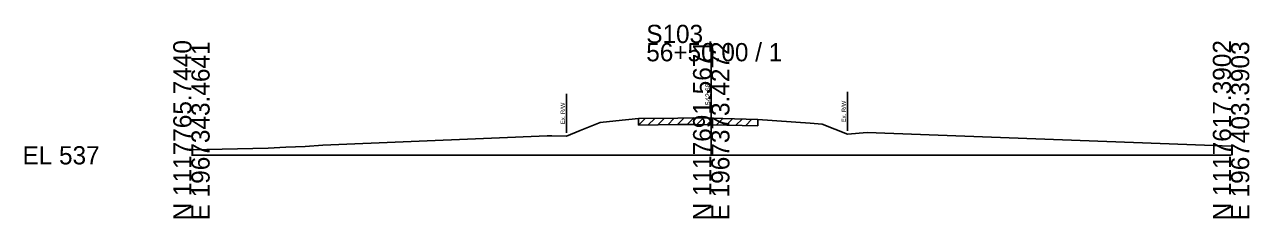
# Model space of a CAD drawing. Extents: x -26 to 163, y -10 to 24018.
# Drawn here: x -25.7 to 162.8, y 5990.3 to 6020.1 of the extents above; entities that cross this region are included whole.
import ezdxf

# ---------------------------------------------------------------- set-up
doc = ezdxf.new("R2010")
doc.units = 0
for name, color, linetype in [('RD_GPK_XS_Cell', 7, 'Continuous'), ('RD_XS_ExGround', 7, 'Continuous'), ('RD_XS_ExPaveRet', 7, 'Continuous'), ('RD_XS_ExRW', 7, 'Continuous'), ('RD_XS_TX_Elev_EX', 7, 'Continuous')]:
    doc.layers.add(name, color=color, linetype=linetype)

msp = doc.modelspace()

# ---------------------------------------------------------------- linework, layer by layer
at = {"layer": 'RD_GPK_XS_Cell'}
for p, q in [((80, 6000), (80, 6017.23)), ((0, 6000), (80, 6000)), ((80, 6000), (160, 6000))]:
    msp.add_line(p, q, dxfattribs=at)
at = {"layer": 'RD_XS_ExGround'}
msp.add_lwpolyline([(0, 6000.86), (11.83, 6001.11), (14.52, 6001.23), (17.5, 6001.37), (20.23, 6001.53), (46.18, 6002.64), (54.73, 6003.01), (55.47, 6003), (57.73, 6002.94), (59.85, 6003.83), (62.93, 6005.03), (65.32, 6005.27), (68.8, 6005.64), (74.88, 6005.72), (77.31, 6005.74), (79.53, 6005.7), (80, 6005.68), (87.19, 6005.52), (95.23, 6004.93), (97.05, 6004.8), (100.98, 6003.24), (104.02, 6003.48), (160, 6001.41)], dxfattribs=at)
at = {"layer": 'RD_XS_ExPaveRet'}
for p, q in [((68.8, 6004.64), (69.81, 6005.65)), ((68.8, 6004.64), (68.8, 6005.64)), ((70.3, 6004.66), (71.31, 6005.67)), ((71.8, 6004.68), (72.81, 6005.69)), ((73.3, 6004.7), (74.31, 6005.71)), ((74.8, 6004.72), (75.81, 6005.73)), ((76.3, 6004.73), (77.31, 6005.74)), ((77.8, 6004.73), (78.78, 6005.71)), ((79.3, 6004.7), (80.28, 6005.68)), ((80.8, 6004.67), (81.77, 6005.64)), ((82.3, 6004.63), (83.27, 6005.61)), ((83.8, 6004.6), (84.77, 6005.57)), ((85.3, 6004.56), (86.27, 6005.54)), ((87.19, 6005.52), (87.19, 6004.52)), ((68.8, 6004.64), (74.88, 6004.72)), ((74.88, 6004.72), (77.31, 6004.74)), ((77.31, 6004.74), (79.53, 6004.7)), ((79.53, 6004.7), (80, 6004.68)), ((80, 6004.68), (87.19, 6004.52))]:
    msp.add_line(p, q, dxfattribs=at)
at = {"layer": 'RD_XS_ExRW'}
for p, q in [((57.73, 6009.44), (57.73, 6003.44)), ((100.98, 6009.74), (100.98, 6003.74))]:
    msp.add_line(p, q, dxfattribs=at)

# ---------------------------------------------------------------- texts
at = {"layer": 'RD_GPK_XS_Cell'}
for s, p in [('S103', (70, 6017.23)), ('56+50.00 / 1', (70, 6014.43)), ('EL 537', (-26, 5998.6))]:
    msp.add_text(s, height=2.8, dxfattribs=at).set_placement(p)
for s, p in [('N 1117765.7440', (0, 5990)), ('E 1967343.4641', (2.8, 5990)), ('N 1117691.5671', (80, 5990)), ('E 1967373.4272', (82.8, 5990)), ('N 1117617.3902', (160, 5990)), ('E 1967403.3903', (162.8, 5990))]:
    msp.add_text(s, height=2.8, rotation=90, dxfattribs=at).set_placement(p)
at = {"layer": 'RD_XS_ExRW'}
for p in [(57.48, 6004.79), (100.73, 6005.08)]:
    msp.add_text('Ex. R/W ', height=0.65, rotation=90, dxfattribs=at).set_placement(p)
at = {"layer": 'RD_XS_TX_Elev_EX'}
msp.add_text('542.68', height=0.8, rotation=90, dxfattribs=at).set_placement((79.9, 6007.68))

doc.saveas('drawing.dxf')
